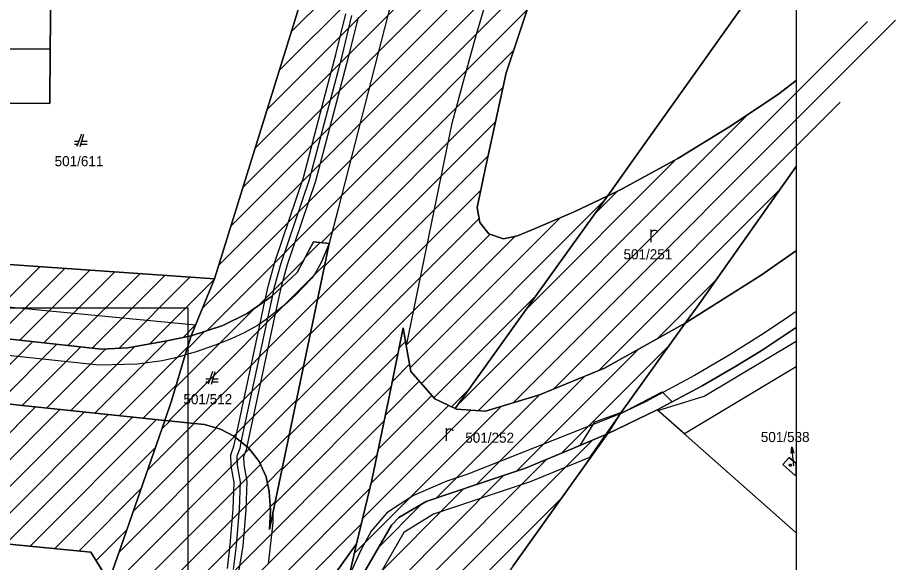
# Model space of a CAD drawing. Extents: x -264309 to -263505, y -1242443 to -1241763.
# Drawn here: x -263712.8 to -263573.6, y -1242090.9 to -1242004.6 of the extents above; entities that cross this region are included whole.
import ezdxf

# ---------------------------------------------------------------- set-up
doc = ezdxf.new("R2010")
doc.units = 0
for name, color, linetype in [('KN_2019_08_16', 7, 'Continuous'), ('KN_2019_08_16_KLADPAR', 7, 'Continuous'), ('KN_2019_08_16_ZAPPAR', 7, 'Continuous'), ('RAM_NA_TLAC_10xA4_1-500', 7, 'Continuous'), ('SRAFY_PARCELY', 7, 'Continuous')]:
    doc.layers.add(name, color=color, linetype=linetype)

msp = doc.modelspace()

# ---------------------------------------------------------------- linework, layer by layer
at = {"layer": 'KN_2019_08_16'}
for p, q in [((-263589.43, -1242041.56), (-263589.31, -1242041.47)), ((-263589.31, -1242041.47), (-263589.31, -1242053.67)), ((-263594.9, -1242045.4), (-263589.43, -1242041.56)), ((-263606.95, -1242052.98), (-263594.9, -1242045.4)), ((-263617.25, -1242067.34), (-263606.95, -1242052.98)), ((-263589.31, -1242053.67), (-263594.9, -1242057.37)), ((-263603.93, -1242064.57), (-263589.31, -1242055.81)), ((-263603.93, -1242064.57), (-263589.31, -1242055.81)), ((-263589.31, -1242055.81), (-263589.31, -1242059.9)), ((-263589.31, -1242055.81), (-263589.31, -1242059.9)), ((-263594.9, -1242057.37), (-263599.06, -1242059.91)), ((-263589.31, -1242059.9), (-263607.07, -1242070.54)), ((-263589.31, -1242059.9), (-263607.07, -1242070.54)), ((-263599.06, -1242059.91), (-263604.22, -1242062.89)), ((-263604.22, -1242062.89), (-263611.4, -1242066.72)), ((-263611.28, -1242066.82), (-263603.93, -1242064.57)), ((-263611.28, -1242066.82), (-263603.93, -1242064.57)), ((-263621.28, -1242068.63), (-263617.12, -1242067.16)), ((-263617.41, -1242067.56), (-263619.66, -1242070.76)), ((-263611.4, -1242066.72), (-263619.25, -1242070.54)), ((-263619.25, -1242070.54), (-263617.25, -1242067.34)), ((-263617.12, -1242067.16), (-263617.41, -1242067.56)), ((-263607.07, -1242070.54), (-263611.28, -1242066.82)), ((-263607.07, -1242070.54), (-263611.28, -1242066.82)), ((-263623.6, -1242072.34), (-263621.28, -1242068.63)), ((-263619.66, -1242070.76), (-263622.12, -1242074.25)), ((-263632.29, -1242075.94), (-263624.38, -1242072.67)), ((-263624.38, -1242072.67), (-263623.6, -1242072.34)), ((-263622.12, -1242074.25), (-263631.55, -1242078.12)), ((-263639.58, -1242078.41), (-263632.29, -1242075.94)), ((-263648.01, -1242081.25), (-263639.58, -1242078.41)), ((-263631.55, -1242078.12), (-263646.86, -1242083.24)), ((-263652.34, -1242083.75), (-263648.01, -1242081.25)), ((-263646.86, -1242083.24), (-263651.55, -1242086.13)), ((-263653.54, -1242084.98), (-263652.34, -1242083.75)), ((-263658.2, -1242093.02), (-263653.54, -1242084.98)), ((-263651.55, -1242086.13), (-263656.21, -1242094.17))]:
    msp.add_line(p, q, dxfattribs=at)
for points in [[(-263658.83, -1242004.48), (-263660.39, -1242010.9), (-263662.24, -1242017.89), (-263665.58, -1242030.48), (-263670.06, -1242043.75), (-263671.09, -1242047.37), (-263671.92, -1242051.25), (-263676.48, -1242072.53), (-263676.59, -1242073.05), (-263677, -1242074.16), (-263676.93, -1242075.39), (-263676.49, -1242078.07), (-263676.63, -1242082.51), (-263677.1, -1242088.32), (-263678.38, -1242095.75), (-263679.14, -1242098.82), (-263680.13, -1242102.51)], [(-263679.55, -1242091.86), (-263679.1, -1242088.12), (-263678.63, -1242082.39), (-263678.49, -1242078.21), (-263678.93, -1242075.61), (-263679.02, -1242073.86), (-263678.51, -1242072.49), (-263678.22, -1242071.12), (-263674.36, -1242053.05), (-263673.59, -1242049.47), (-263673.05, -1242046.96), (-263671.98, -1242043.15), (-263667.5, -1242029.9), (-263664.18, -1242017.37), (-263662.33, -1242010.4), (-263660.77, -1242003.98)], [(-263678.56, -1242092.03), (-263678.1, -1242088.22), (-263677.63, -1242082.45), (-263677.49, -1242078.14), (-263677.93, -1242075.5), (-263678.01, -1242074.01), (-263677.55, -1242072.77), (-263677.35, -1242071.82), (-263673.15, -1242052.21), (-263672.37, -1242048.58), (-263672.08, -1242047.2), (-263671.02, -1242043.45), (-263666.54, -1242030.19), (-263663.21, -1242017.63), (-263661.36, -1242010.65), (-263659.8, -1242004.23)]]:
    msp.add_lwpolyline(points, dxfattribs=at)
msp.add_lwpolyline([(-263619.25, -1242070.54), (-263617.25, -1242067.34), (-263610.6, -1242063.86), (-263609.01, -1242065.44), (-263611.4, -1242066.72)], close=True, dxfattribs=at)
at = {"layer": 'KN_2019_08_16_KLADPAR'}
for p, q in [((-263589.31, -1241990.93), (-263589.31, -1242014.51)), ((-263596.1, -1242000.33), (-263606.1, -1242014.38)), ((-263606.1, -1242014.38), (-263596.1, -1242000.33)), ((-263635.33, -1242013.32), (-263631.39, -1242001.36)), ((-263638.74, -1242028.84), (-263635.33, -1242013.32)), ((-263606.1, -1242014.38), (-263613.7, -1242025.06)), ((-263613.7, -1242025.06), (-263606.1, -1242014.38)), ((-263592.28, -1242016.8), (-263589.31, -1242014.51)), ((-263589.31, -1242014.51), (-263592.28, -1242016.8)), ((-263589.31, -1242014.51), (-263589.31, -1242028.13)), ((-263599.99, -1242021.94), (-263592.28, -1242016.8)), ((-263592.28, -1242016.8), (-263599.99, -1242021.94)), ((-263608.12, -1242026.9), (-263599.99, -1242021.94)), ((-263599.99, -1242021.94), (-263608.12, -1242026.9)), ((-263702.72, -1242023.01), (-263703.42, -1242025.01)), ((-263702.92, -1242025.01), (-263702.32, -1242023.01)), ((-263703.14, -1242024.21), (-263703.82, -1242024.21)), ((-263703.82, -1242024.61), (-263703.28, -1242024.61)), ((-263702.8, -1242024.61), (-263701.82, -1242024.61)), ((-263701.82, -1242024.21), (-263702.68, -1242024.21)), ((-263613.7, -1242025.06), (-263619.28, -1242032.85)), ((-263619.28, -1242032.85), (-263613.7, -1242025.06)), ((-263616.91, -1242031.71), (-263608.12, -1242026.9)), ((-263608.12, -1242026.9), (-263616.91, -1242031.71)), ((-263639.94, -1242034.66), (-263638.74, -1242028.84)), ((-263589.31, -1242028.13), (-263605.02, -1242050.41)), ((-263605.02, -1242050.41), (-263589.31, -1242028.13)), ((-263589.31, -1242028.13), (-263589.31, -1242041.47)), ((-263619.28, -1242032.85), (-263616.91, -1242031.71)), ((-263616.91, -1242031.71), (-263619.28, -1242032.85)), ((-263628.45, -1242045.64), (-263619.28, -1242032.85)), ((-263619.31, -1242032.86), (-263624.53, -1242035.34)), ((-263619.28, -1242032.85), (-263619.31, -1242032.86)), ((-263639.5, -1242037.05), (-263639.94, -1242034.66)), ((-263624.53, -1242035.34), (-263630.73, -1242038)), ((-263638.09, -1242038.83), (-263639.5, -1242037.05)), ((-263630.73, -1242038), (-263633.55, -1242039.15)), ((-263635.78, -1242039.62), (-263638.09, -1242038.83)), ((-263633.55, -1242039.15), (-263635.78, -1242039.62)), ((-263589.31, -1242041.47), (-263589.43, -1242041.56)), ((-263589.43, -1242041.56), (-263594.9, -1242045.4)), ((-263643.45, -1242066.48), (-263628.45, -1242045.64)), ((-263594.9, -1242045.4), (-263606.95, -1242052.98)), ((-263605.02, -1242050.41), (-263606.95, -1242052.98)), ((-263606.95, -1242052.98), (-263605.02, -1242050.41)), ((-263606.95, -1242052.98), (-263619.73, -1242060.13)), ((-263594.9, -1242057.37), (-263589.31, -1242053.67)), ((-263589.31, -1242053.67), (-263589.31, -1242086.21)), ((-263599.06, -1242059.91), (-263594.9, -1242057.37)), ((-263681.9, -1242060.66), (-263682.6, -1242062.66)), ((-263682.1, -1242062.66), (-263681.5, -1242060.66)), ((-263619.73, -1242060.13), (-263630.05, -1242064.33)), ((-263604.22, -1242062.89), (-263599.06, -1242059.91)), ((-263682.32, -1242061.86), (-263683, -1242061.86)), ((-263683, -1242062.26), (-263682.46, -1242062.26)), ((-263681.98, -1242062.26), (-263681, -1242062.26)), ((-263681, -1242061.86), (-263681.86, -1242061.86)), ((-263611.4, -1242066.72), (-263604.22, -1242062.89)), ((-263630.05, -1242064.33), (-263638.63, -1242066.92)), ((-263643.2, -1242066.6), (-263643.45, -1242066.48)), ((-263638.63, -1242066.92), (-263643.2, -1242066.6)), ((-263619.25, -1242070.54), (-263611.4, -1242066.72)), ((-263611.4, -1242066.72), (-263589.31, -1242086.21)), ((-263589.31, -1242086.21), (-263611.4, -1242066.72)), ((-263634.2, -1242091.43), (-263619.25, -1242070.54)), ((-263590.11, -1242073.6), (-263590.01, -1242072.58)), ((-263591.43, -1242075.39), (-263590.43, -1242074.26)), ((-263590.43, -1242074.26), (-263591.43, -1242075.39)), ((-263590.43, -1242074.26), (-263589.31, -1242075.24)), ((-263589.31, -1242075.24), (-263590.43, -1242074.26)), ((-263589.47, -1242077.12), (-263591.43, -1242075.39)), ((-263591.43, -1242075.39), (-263589.47, -1242077.12)), ((-263589.31, -1242075.24), (-263589.31, -1242076.94)), ((-263589.31, -1242076.94), (-263589.31, -1242075.24)), ((-263589.31, -1242076.94), (-263589.47, -1242077.12)), ((-263589.47, -1242077.12), (-263589.31, -1242076.94)), ((-263589.31, -1242086.21), (-263589.31, -1242136.09))]:
    msp.add_line(p, q, dxfattribs=at)
for points in [[(-263707.47, -1241991.99), (-263664.79, -1241992.08), (-263667.36, -1242000.21), (-263681.58, -1242045.97), (-263742.18, -1242041.73), (-263746.1, -1242041.26), (-263746.03, -1242018.11), (-263707.74, -1242018.19), (-263707.65, -1242009.54)], [(-263746.07, -1242009.46), (-263707.65, -1242009.54), (-263707.74, -1242018.19), (-263746.03, -1242018.11)], [(-263689.5, -1242068.4), (-263688.36, -1242065.12), (-263686.23, -1242058.02), (-263685.32, -1242054.97), (-263680.26, -1242053.33), (-263676.43, -1242051.46), (-263672.57, -1242048.76), (-263668.51, -1242044.94), (-263665.87, -1242040.07), (-263663.39, -1242040.38), (-263663.87, -1242042.7), (-263672.35, -1242083.11), (-263672.89, -1242085.66), (-263672.73, -1242082.62), (-263672.92, -1242079.63), (-263673.38, -1242077.33), (-263674.53, -1242074.91), (-263676.21, -1242072.75), (-263678.51, -1242070.88), (-263680.64, -1242069.77), (-263683.2, -1242069.06)], [(-263659.07, -1242087.95), (-263656.62, -1242077.85), (-263653.93, -1242064.92), (-263651.67, -1242053.72), (-263651.18, -1242056.5), (-263650.46, -1242060.65), (-263646.65, -1242064.99), (-263643.45, -1242066.48), (-263643.2, -1242066.6), (-263638.63, -1242066.92), (-263630.05, -1242064.33), (-263619.73, -1242060.13), (-263606.95, -1242052.98), (-263617.25, -1242067.34), (-263619.25, -1242070.54), (-263624.38, -1242072.67), (-263632.29, -1242075.94), (-263639.58, -1242078.41), (-263648.01, -1242081.25), (-263652.34, -1242083.75), (-263653.54, -1242084.98), (-263658.2, -1242093.02), (-263659.63, -1242093.02), (-263660.26, -1242093.02)], [(-263590.16, -1242075.34), (-263590.07, -1242075.49), (-263590.16, -1242075.64), (-263590.34, -1242075.64), (-263590.43, -1242075.49), (-263590.34, -1242075.34)], [(-263766.58, -1242082.89), (-263701.19, -1242089.29), (-263698.34, -1242093.87), (-263688.51, -1242109.63), (-263692.31, -1242120.01), (-263699.84, -1242134.09), (-263703.22, -1242140.34), (-263706.87, -1242146.12), (-263713.18, -1242156.13), (-263748.89, -1242212.77), (-263757.19, -1242207.25), (-263758.42, -1242206.43), (-263766.58, -1242201.01), (-263766.58, -1242144.85), (-263766.58, -1242122.39), (-263766.58, -1242113.95), (-263766.58, -1242093.5)]]:
    msp.add_lwpolyline(points, close=True, dxfattribs=at)
for points in [[(-263707.47, -1241991.99), (-263707.65, -1242009.54), (-263746.07, -1242009.46), (-263746.09, -1242004.16)], [(-263698.34, -1242093.87), (-263696.42, -1242088.33), (-263689.5, -1242068.4), (-263683.2, -1242069.06), (-263680.64, -1242069.77), (-263678.51, -1242070.88), (-263676.21, -1242072.75), (-263674.53, -1242074.91), (-263673.38, -1242077.33), (-263672.92, -1242079.63), (-263672.73, -1242082.62), (-263672.89, -1242085.66), (-263672.35, -1242083.11), (-263663.87, -1242042.7), (-263663.39, -1242040.38), (-263665.87, -1242040.07), (-263668.51, -1242044.94), (-263672.57, -1242048.76), (-263676.43, -1242051.46), (-263680.26, -1242053.33), (-263685.32, -1242054.97), (-263684.63, -1242053.31), (-263681.58, -1242045.97), (-263667.36, -1242000.21)], [(-263631.39, -1242001.36), (-263635.33, -1242013.32), (-263638.74, -1242028.84), (-263639.94, -1242034.66), (-263639.5, -1242037.05), (-263638.09, -1242038.83), (-263635.78, -1242039.62), (-263633.55, -1242039.15), (-263630.73, -1242038), (-263624.53, -1242035.34), (-263619.31, -1242032.86), (-263619.28, -1242032.85), (-263628.45, -1242045.64), (-263643.45, -1242066.48), (-263646.65, -1242064.99), (-263650.46, -1242060.65), (-263651.18, -1242056.5), (-263651.67, -1242053.72), (-263653.93, -1242064.92), (-263656.62, -1242077.85), (-263659.07, -1242087.95), (-263670.14, -1242103.34)], [(-263829.96, -1242032.95), (-263750.04, -1242040.89), (-263746.1, -1242041.26), (-263742.18, -1242041.73), (-263681.58, -1242045.97), (-263684.63, -1242053.31), (-263685.32, -1242054.97), (-263689.17, -1242055.8), (-263695.33, -1242056.9), (-263699.55, -1242057.11), (-263715.96, -1242055.32), (-263736.94, -1242052.97), (-263758.51, -1242050.91), (-263773.94, -1242049.27), (-263789.68, -1242047.57)], [(-263612.32, -1242040.16), (-263612.32, -1242038.89), (-263612.32, -1242038.16)], [(-263612.32, -1242038.56), (-263612.22, -1242038.43), (-263612.09, -1242038.32), (-263611.95, -1242038.27), (-263611.72, -1242038.26), (-263611.55, -1242038.29), (-263611.45, -1242038.36), (-263611.36, -1242038.46), (-263611.32, -1242038.56)], [(-263589.31, -1242053.67), (-263594.9, -1242057.37), (-263599.06, -1242059.91), (-263604.22, -1242062.89), (-263611.4, -1242066.72), (-263619.25, -1242070.54), (-263617.25, -1242067.34), (-263606.95, -1242052.98), (-263594.9, -1242045.4), (-263589.43, -1242041.56), (-263589.31, -1242041.47)], [(-263789.68, -1242047.57), (-263773.94, -1242049.27), (-263758.51, -1242050.91), (-263736.94, -1242052.97), (-263715.96, -1242055.32), (-263699.55, -1242057.11), (-263695.33, -1242056.9), (-263689.17, -1242055.8), (-263685.32, -1242054.97), (-263686.23, -1242058.02), (-263688.36, -1242065.12), (-263689.5, -1242068.4), (-263736.68, -1242063.45), (-263782.02, -1242058.63), (-263784.04, -1242058.41), (-263791.13, -1242057.66)], [(-263801.28, -1242075.1), (-263785.17, -1242077.19), (-263784.12, -1242072.3), (-263781.45, -1242072.38), (-263780.92, -1242070.3), (-263775.63, -1242071.05), (-263775.43, -1242063.83), (-263782.64, -1242063.41), (-263782.02, -1242058.63), (-263736.68, -1242063.45), (-263689.5, -1242068.4), (-263696.42, -1242088.33), (-263698.34, -1242093.87), (-263701.19, -1242089.29), (-263766.58, -1242082.89), (-263766.58, -1242093.5), (-263766.58, -1242113.95), (-263766.58, -1242122.39), (-263766.58, -1242144.85), (-263804.58, -1242145.58)], [(-263711.04, -1242160.22), (-263700.71, -1242145.84), (-263697.71, -1242141.67), (-263681.94, -1242119.74), (-263670.14, -1242103.34), (-263659.07, -1242087.95), (-263660.26, -1242093.02), (-263659.63, -1242093.02), (-263658.2, -1242093.02), (-263653.54, -1242084.98), (-263652.34, -1242083.75), (-263648.01, -1242081.25), (-263639.58, -1242078.41), (-263632.29, -1242075.94), (-263624.38, -1242072.67), (-263619.25, -1242070.54), (-263634.2, -1242091.43), (-263637.5, -1242095.97), (-263666.12, -1242137.18), (-263678.83, -1242155.48)], [(-263644.78, -1242071.64), (-263644.78, -1242070.37), (-263644.78, -1242069.64)], [(-263644.78, -1242070.04), (-263644.68, -1242069.91), (-263644.55, -1242069.8), (-263644.41, -1242069.75), (-263644.18, -1242069.74), (-263644.01, -1242069.77), (-263643.91, -1242069.84), (-263643.82, -1242069.94), (-263643.78, -1242070.04)], [(-263589.73, -1242075.57), (-263590.01, -1242072.58), (-263589.72, -1242073.56)]]:
    msp.add_lwpolyline(points, dxfattribs=at)
at = {"layer": 'KN_2019_08_16_ZAPPAR'}
for p, q in [((-263684.63, -1242053.31), (-263742.26, -1242047.78)), ((-263670.49, -1242050.13), (-263673.42, -1242052.42)), ((-263617.25, -1242067.34), (-263641.41, -1242076.9))]:
    msp.add_line(p, q, dxfattribs=at)
for points in [[(-263629.01, -1241980.26), (-263634.11, -1241990.21), (-263637.9, -1241999.88), (-263640.1, -1242007.24), (-263642.22, -1242014.92), (-263643.99, -1242021.55), (-263651.18, -1242056.5)], [(-263653.04, -1242000), (-263661.96, -1242034.89), (-263663.39, -1242040.38)], [(-263663.39, -1242040.38), (-263664.61, -1242043.25), (-263665.58, -1242045.01), (-263666.2, -1242045.91), (-263668.74, -1242048.55), (-263670.49, -1242050.13)], [(-263784.51, -1242050.62), (-263726.8, -1242056.75), (-263699.93, -1242059.57), (-263693.82, -1242059.4), (-263689.88, -1242058.88), (-263687.3, -1242058.33), (-263686.23, -1242058.02)], [(-263589.31, -1242051.14), (-263590.55, -1242052), (-263594.59, -1242054.68), (-263599.95, -1242058.04), (-263605.48, -1242061.28), (-263613.23, -1242065.43), (-263617.25, -1242067.34)], [(-263673.42, -1242052.42), (-263674.79, -1242053.35), (-263676.88, -1242054.52), (-263678.98, -1242055.47), (-263681.52, -1242056.48), (-263684.66, -1242057.56), (-263686.23, -1242058.02)], [(-263641.41, -1242076.9), (-263644.77, -1242078.04), (-263650.02, -1242080.28), (-263654.27, -1242083.02), (-263656.75, -1242085.95), (-263658.33, -1242088.82), (-263660.26, -1242093.02)], [(-263672.35, -1242083.11), (-263672.36, -1242084.58), (-263673.09, -1242091.19)]]:
    msp.add_lwpolyline(points, dxfattribs=at)
at = {"layer": 'RAM_NA_TLAC_10xA4_1-500'}
msp.add_lwpolyline([(-264210.83, -1242050.54), (-264105.83, -1242050.54), (-264000.83, -1242050.54), (-263895.83, -1242050.54), (-263790.83, -1242050.54), (-263685.83, -1242050.54), (-263685.83, -1242199.04), (-263685.83, -1242347.54), (-263790.83, -1242347.54), (-263895.83, -1242347.54), (-264000.83, -1242347.54), (-264105.83, -1242347.54), (-264210.83, -1242347.54), (-264210.83, -1242199.04)], close=True, dxfattribs=at)
at = {"layer": 'SRAFY_PARCELY'}
for p, q in [((-263669.41, -1242006.79), (-263586.35, -1241923.74)), ((-263671.32, -1242012.95), (-263589.58, -1241931.21)), ((-263673.23, -1242019.1), (-263586.87, -1241932.74)), ((-263675.14, -1242025.26), (-263602.92, -1241953.03)), ((-263677.06, -1242031.42), (-263610.38, -1241964.74)), ((-263678.97, -1242037.57), (-263618.47, -1241977.07)), ((-263680.88, -1242043.73), (-263624.95, -1241987.79)), ((-263683.5, -1242050.58), (-263628.87, -1241995.96)), ((-263682.84, -1242054.17), (-263632.06, -1242003.39)), ((-263639.72, -1242066.84), (-263578.04, -1242005.17)), ((-263634.22, -1242065.59), (-263573.59, -1242004.96)), ((-263664.65, -1242040.22), (-263634.14, -1242009.71)), ((-263664.13, -1242043.95), (-263635.84, -1242015.66)), ((-263627.8, -1242063.42), (-263582.34, -1242017.95)), ((-263643.08, -1242065.96), (-263597.18, -1242020.07)), ((-263665.26, -1242049.31), (-263637.04, -1242021.09)), ((-263666.38, -1242054.68), (-263638.23, -1242026.53)), ((-263632.18, -1242050.82), (-263608.42, -1242027.07)), ((-263620.65, -1242060.5), (-263591.79, -1242031.64)), ((-263667.51, -1242060.05), (-263639.37, -1242031.92)), ((-263621.38, -1242035.78), (-263617.68, -1242032.08)), ((-263648.79, -1242062.55), (-263619.75, -1242033.5)), ((-263668.64, -1242065.42), (-263639.62, -1242036.4)), ((-263650.56, -1242060.07), (-263626.8, -1242036.32)), ((-263669.77, -1242070.79), (-263637.88, -1242038.9)), ((-263651.19, -1242056.46), (-263633.97, -1242039.24)), ((-263667.27, -1242042.65), (-263664.82, -1242040.2)), ((-263720.14, -1242054.85), (-263709.32, -1242044.03)), ((-263688.85, -1242068.47), (-263664.08, -1242043.7)), ((-263674.63, -1242050.2), (-263667.49, -1242043.06)), ((-263716.32, -1242055.28), (-263705.35, -1242044.31)), ((-263712.5, -1242055.7), (-263701.39, -1242044.58)), ((-263708.67, -1242056.11), (-263697.42, -1242044.86)), ((-263704.85, -1242056.53), (-263693.46, -1242045.14)), ((-263701.02, -1242056.95), (-263689.49, -1242045.42)), ((-263696.8, -1242056.97), (-263685.52, -1242045.69)), ((-263691.87, -1242056.28), (-263681.6, -1242046.01)), ((-263611.33, -1242055.43), (-263601.93, -1242046.03)), ((-263685.01, -1242068.87), (-263665.21, -1242049.07)), ((-263646.81, -1242064.81), (-263630.52, -1242048.52)), ((-263687.77, -1242063.15), (-263675.27, -1242050.65)), ((-263686.59, -1242055.24), (-263684.61, -1242053.27)), ((-263685.95, -1242057.09), (-263683.12, -1242054.26)), ((-263681.44, -1242069.55), (-263666.33, -1242054.44)), ((-263719.77, -1242065.22), (-263710.46, -1242055.92)), ((-263715.93, -1242065.63), (-263706.64, -1242056.34)), ((-263712.09, -1242066.03), (-263702.81, -1242056.75)), ((-263704.41, -1242066.84), (-263694.29, -1242056.71)), ((-263700.57, -1242067.24), (-263689.12, -1242055.79)), ((-263696.73, -1242067.64), (-263685.86, -1242056.77)), ((-263652.31, -1242056.89), (-263651.29, -1242055.87)), ((-263626.56, -1242073.57), (-263609.44, -1242056.45)), ((-263708.25, -1242066.43), (-263698.89, -1242057.08)), ((-263670.89, -1242076.16), (-263652.48, -1242057.75)), ((-263633.62, -1242076.39), (-263614.36, -1242057.12)), ((-263653.38, -1242062.21), (-263650.66, -1242059.49)), ((-263678.52, -1242070.87), (-263667.46, -1242059.81)), ((-263654.48, -1242067.55), (-263649.11, -1242062.18)), ((-263640.04, -1242078.56), (-263622.89, -1242061.42)), ((-263692.89, -1242068.04), (-263687.67, -1242062.83)), ((-263672.02, -1242081.53), (-263653.56, -1242063.07)), ((-263643.99, -1242066.23), (-263641.42, -1242063.66)), ((-263676.19, -1242072.78), (-263668.59, -1242065.18)), ((-263655.59, -1242072.9), (-263647.13, -1242064.44)), ((-263646.44, -1242080.72), (-263630.05, -1242064.33)), ((-263730.18, -1242086.45), (-263709.97, -1242066.25)), ((-263659.43, -1242089.47), (-263636.12, -1242066.16)), ((-263656.72, -1242078.28), (-263644.46, -1242066.01)), ((-263726.31, -1242086.83), (-263706.13, -1242066.65)), ((-263722.45, -1242087.21), (-263702.3, -1242067.06)), ((-263718.58, -1242087.59), (-263698.46, -1242067.46)), ((-263714.72, -1242087.97), (-263694.62, -1242067.86)), ((-263658.08, -1242083.88), (-263640.96, -1242066.76)), ((-263710.85, -1242088.34), (-263690.78, -1242068.27)), ((-263692.24, -1242076.3), (-263684.83, -1242068.89)), ((-263691.34, -1242105.09), (-263654.66, -1242068.41)), ((-263689.99, -1242069.8), (-263688.67, -1242068.49)), ((-263694.5, -1242082.8), (-263681.29, -1242069.59)), ((-263674.38, -1242075.22), (-263669.71, -1242070.55)), ((-263619.31, -1242070.57), (-263619.19, -1242070.44)), ((-263696.76, -1242089.3), (-263678.42, -1242070.96)), ((-263685.83, -1242135.72), (-263621.63, -1242071.53)), ((-263706.99, -1242088.72), (-263691.01, -1242072.74)), ((-263697.86, -1242094.64), (-263676.1, -1242072.89)), ((-263689.71, -1242107.71), (-263655.77, -1242073.77)), ((-263685.83, -1242131.48), (-263628.87, -1242074.53)), ((-263696.23, -1242097.26), (-263674.32, -1242075.35)), ((-263673.19, -1242078.27), (-263670.84, -1242075.92)), ((-263685.83, -1242127.24), (-263635.68, -1242077.09)), ((-263694.6, -1242099.87), (-263673.16, -1242078.43)), ((-263703.12, -1242089.1), (-263693.26, -1242079.24)), ((-263689.16, -1242111.4), (-263656.94, -1242079.18)), ((-263680.32, -1242117.49), (-263642.09, -1242079.25)), ((-263685.83, -1242139.96), (-263626.42, -1242080.56)), ((-263672.76, -1242082.08), (-263671.97, -1242081.29)), ((-263655.59, -1242088.51), (-263648.75, -1242081.68)), ((-263692.97, -1242102.48), (-263672.75, -1242082.26)), ((-263700.38, -1242090.6), (-263695.52, -1242085.74)), ((-263691.61, -1242118.09), (-263658.3, -1242084.79))]:
    msp.add_line(p, q, dxfattribs=at)

# ---------------------------------------------------------------- texts
at = {"layer": 'KN_2019_08_16_KLADPAR'}
for s, p in [('501/611', (-263706.96, -1242028.11)), ('501/251', (-263616.72, -1242042.87)), ('501/512', (-263686.53, -1242065.82)), ('501/252', (-263641.82, -1242071.93)), ('501/538', (-263594.94, -1242071.82))]:
    msp.add_text(s, height=1.6, dxfattribs=at).set_placement(p)

doc.saveas('drawing.dxf')
